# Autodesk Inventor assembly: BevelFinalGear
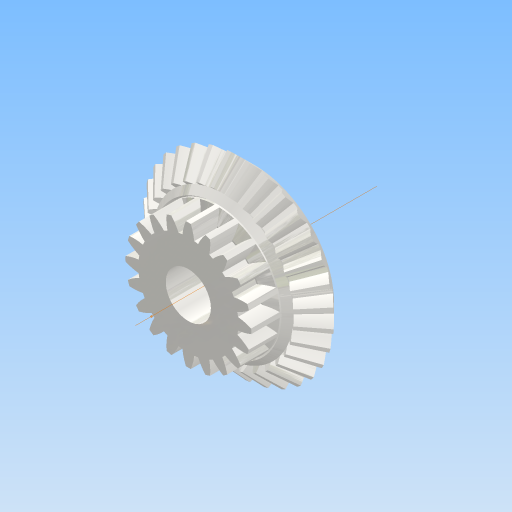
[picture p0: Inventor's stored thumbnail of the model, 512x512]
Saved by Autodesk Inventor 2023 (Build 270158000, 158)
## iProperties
Created: 2024-01
Part Number: BevelFinalGear
Document SubType Name: Assembly
Designer: kumagai
Author: kumagai
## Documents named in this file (3)
- \\192.168.3.8\kumagai\Develop\CAD\NakataOmni\DriveUnitR3\BevelFinalGear.iam
- \\192.168.3.8\kumagai\Develop\CAD\NakataOmni\DriveUnitR3\FinalGear.ipt
- \\192.168.3.8\kumagai\Develop\CAD\NakataOmni\DriveUnitR3\BevelGear_32_V.ipt
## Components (2 placed, 2 different names)
1. かさ歯車1:1 — メイト:2
2. 平歯車2:1 — メイト:2
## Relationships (1: Mate 1)
- メイト:2 [Mate]: かさ歯車1:1 ↔ 平歯車2:1
